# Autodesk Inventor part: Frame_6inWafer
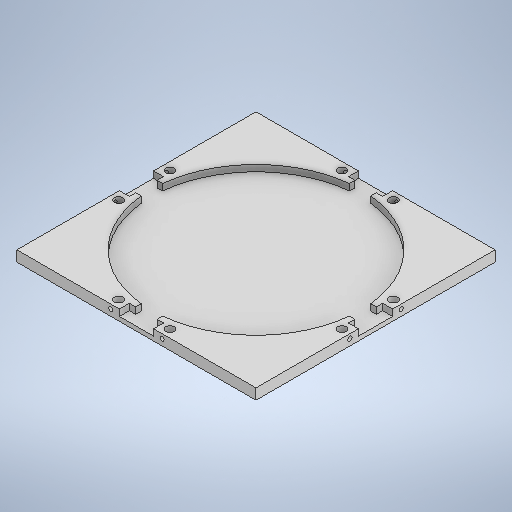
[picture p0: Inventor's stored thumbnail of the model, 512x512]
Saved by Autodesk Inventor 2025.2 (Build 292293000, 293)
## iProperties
Created: 2025-09
Part Number: Frame_6inWafer
Material: Generic
Document SubType Name: Modeling
Designer: tyler
Density: 1 g/cm^3
Appearance: Default
Author: tyler
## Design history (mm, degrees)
sketch "Sketch1"
  geometry: L1 (88.9, 88.9)-(88.9, -88.9); L2 (88.9, -88.9)-(-88.9, -88.9); L3 (-88.9, -88.9)-(-88.9, 88.9); L4 (-88.9, 88.9)-(88.9, -88.9); L5 (88.9, 88.9)-(-88.9, -88.9); L6 (0, 88.9)-(12.7, 88.9); L7 (12.7, 88.9)-(12.7, 76.744); L8 (0, 88.9)-(-12.7, 88.9); L9 (-12.7, 88.9)-(-12.7, 76.744); L10 (12.7, 81.506)-(7.938, 81.506); L11 (7.938, 81.506)-(7.938, 77.381); L12 (12.7, 76.744)-(12.7, 81.506); L13 (-12.7, 76.744)-(-12.7, 81.506); L14 (-12.7, 81.506)-(-7.938, 81.506); L15 (-7.938, 81.506)-(-7.938, 77.381); L16 (-88.9, 12.7)-(-76.744, 12.7); L17 (-81.506, 12.7)-(-81.506, 7.938); L18 (-81.506, 7.938)-(-77.381, 7.938); L19 (-88.9, 0)-(-88.9, 12.7); L20 (-88.9, 0)-(-88.9, -12.7); L21 (-88.9, -12.7)-(-76.744, -12.7); L22 (-81.506, -12.7)-(-81.506, -7.937); L23 (-81.506, -7.937)-(-77.381, -7.937); L24 (-12.7, -88.9)-(-12.7, -76.744); L25 (-12.7, -81.506)-(-7.938, -81.506); L26 (-7.938, -81.506)-(-7.938, -77.381); L27 (0, -88.9)-(-12.7, -88.9); L28 (0, -88.9)-(12.7, -88.9); L29 (12.7, -88.9)-(12.7, -76.744); L30 (12.7, -81.506)-(7.937, -81.506); L31 (7.937, -81.506)-(7.937, -77.381); L32 (88.9, -12.7)-(76.744, -12.7); L33 (81.506, -12.7)-(81.506, -7.938); L34 (81.506, -7.938)-(77.381, -7.938); L35 (88.9, 0)-(88.9, -12.7); L36 (88.9, 0)-(88.9, 12.7); L37 (88.9, 12.7)-(76.744, 12.7); L38 (81.506, 12.7)-(81.506, 7.937); L39 (81.506, 7.937)-(77.381, 7.937); L40 (88.9, 88.9)-(-88.9, 88.9); C1 r 76.2 at (0, 0); A1 r 77.788 centre (0, 0) between (12.7, 76.744) and (-12.7, 76.744); 15 further points
  constraints: 80 end point, 8 point on line, 5 perpendicular, 5 point on circle, 2 centre point, 2 coincident, 2 horizontal, 2 midpoint, 1 parallel, 1 vertical, 77 other
  dimensions: "d0" = 177.8 distance of L1.end L2.end; "d1" = 177.8 distance of L1.start L1.end; "d2" = 152.4 diameter of C1; "d3" = 155.575 diameter of A1; "d4" = 12.7 distance of L6.start L6.end; "d7" = 4.7625 distance of L10.start L10.end; "d8" = 4.7625 distance of L7.end L10.start; "d9" = 4.7625 distance of L13.end L14.end; "d12" = 360 deg dimension on point (0, 0) L6.end (derived)
  node "Sketch Circular Pattern1" dims "d12" = 360 deg (derived)
sketch "Sketch2"
  geometry: L1 (-88.9, -88.9)-(88.9, -88.9); L2 (88.9, -88.9)-(88.9, 88.9); L3 (88.9, 88.9)-(-88.9, 88.9); L4 (-88.9, 88.9)-(-88.9, -88.9); L5 (-88.9, -88.9)-(88.9, 88.9); L6 (88.9, -88.9)-(-88.9, 88.9); 1 further point
  constraints: 12 end point, 2 midpoint, 2 parallel, 1 horizontal, 1 perpendicular
  dimensions: "d14" = 177.8 distance of L3.end L2.end; "d15" = 177.8 distance of L2.end L1.end
extrude "Extrusion1" new body sketch "Sketch2" distance "d16" = 3.175; taper "d17" = 0 deg
extrude "Extrusion2" join sketch "Sketch1" distance "d18" = 4.7625; taper "d19" = 0 deg
sketch "Sketch3"
  geometry: L1 (0, -83.058)-(19.05, -83.058); L2 (0, -83.058)-(-19.05, -83.058); L3 (-12.7, -88.9)-(12.7, -88.9) reference; L4 (0, -88.9)-(0, -83.058); C1 r 3.175 at (-19.05, -83.058); C2 r 3.175 at (19.05, -83.058); C3 r 3.175 at (83.058, -19.05); C4 r 3.175 at (83.058, 19.05); C5 r 3.175 at (19.05, 83.058); C6 r 3.175 at (-19.05, 83.058); C7 r 3.175 at (-83.058, 19.05); C8 r 3.175 at (-83.058, -19.05); 1 further point
  constraints: 8 centre point, 6 end point, 2 coincident, 2 horizontal, 1 midpoint, 1 perpendicular, 17 other
  dimensions: "d29" = 19.05 distance of L1.start L1.end; "d30" = 19.05 distance of L1.start L2.end; "d31" = 6.35 diameter of C1; "d32" = 6.35 diameter of C2; "d33" = 5.842 distance of L4.start L1.start; "d36" = 360 deg dimension on point (0, 0) C1.centre (derived)
extrude "Extrusion3" cut sketch "Sketch3" distance "d38" = 6.35; taper "d39" = 0 deg
sketch "Sketch4"
  geometry: L1 (177.8, 0)-(0, 0) reference; L2 (88.9, 0)-(63.5, 0); L3 (88.9, 0)-(114.3, 0); L4 (63.5, 0)-(69.85, 0); L5 (114.3, 0)-(107.95, 0); L6 (0, 7.938)-(76.2, 7.938) reference; L7 (101.6, 7.938)-(177.8, 7.938) reference; C1 r 1.587 at (69.85, 4.762); C2 r 1.587 at (107.95, 4.762); 1 further point
  constraints: 8 end point, 4 point on line, 2 centre point, 1 midpoint
  dimensions: "d40" = 25.4 distance of L2.start L2.end; "d41" = 25.4 distance of L2.start L3.end; "d44" = 6.35 distance of L4.end L2.end; "d45" = 6.35 distance of L5.end L3.end; "d46" = 3.175 diameter of C1; "d47" = 3.175 diameter of C2; "d76" = 3.175 distance from line of C1.centre L6; "d77" = 3.175 distance from line of L7 C2.centre
extrude "Extrusion4" cut sketch "Sketch4" distance "d48" = 6.35; taper "d49" = 0 deg
sketch "Sketch5"
  geometry: L1 (177.8, 0)-(0, 0) reference; L2 (88.9, 0)-(63.5, 0); L3 (63.5, 0)-(63.5, 4.762); L4 (63.5, 4.762)-(69.85, 4.763); L5 (88.9, 0)-(114.3, 0); L6 (114.3, 3.175)-(107.95, 3.175); L7 (166.281, 3.175)-(96.838, 3.175) reference; L8 (0, 7.938)-(76.2, 7.938) reference; L9 (107.95, 7.938)-(107.95, 4.763); C1 r 1.588 at (69.85, 4.763); 2 further points
  constraints: 12 end point, 3 point on line, 2 coincident, 2 perpendicular, 1 centre point, 1 midpoint, 1 vertical, 1 vertical alignment, 2 other
  dimensions: "d50" = 25.4 distance of L2.start L2.end; "d52" = 6.35 distance of L3.end L4.end; "d56" = 3.175 diameter of C1; "d78" = 3.175 distance from line of L8 L4.end
extrude "Extrusion5" cut sketch "Sketch5" distance "d58" = 6.35; taper "d59" = 0 deg
sketch "Sketch6"
  geometry: L1 (0, 0)-(177.8, 0) reference; L2 (88.9, 0)-(63.5, 0); L3 (80.963, 3.175)-(11.519, 3.175) reference; L4 (69.85, 3.175)-(107.95, 3.175); L5 (166.281, 3.175)-(96.838, 3.175) reference; L6 (76.2, 7.938)-(0, 7.938) reference; L7 (69.85, 7.938)-(69.85, 4.763); L8 (104.775, 7.938)-(111.125, 7.938) reference; L9 (107.95, 7.938)-(107.95, 4.763); C1 r 1.587 at (69.85, 4.763); C2 r 1.588 at (107.95, 4.763); 1 further point
  constraints: 8 end point, 4 point on line, 2 centre point, 2 coincident, 2 midpoint, 1 vertical, 1 vertical alignment, 1 other
  dimensions: "d79" = 3.175 distance of L7.start L7.end; "d80" = 3.175 distance of L9.start L9.end (derived); "d81" = 3.175 diameter of C1
extrude "Extrusion6" cut sketch "Sketch6" distance "d66" = 6.35; taper "d67" = 0 deg
sketch "Sketch7"
  geometry: L1 (0, 0)-(177.8, 0) reference; L2 (88.9, 0)-(63.5, 0); L3 (63.5, 4.762)-(69.85, 4.762); L4 (69.85, 4.762)-(107.95, 4.762); L5 (69.85, 4.762)-(69.85, 7.938); L6 (66.675, 7.938)-(73.025, 7.938) reference; C1 r 1.587 at (69.85, 4.762); C2 r 1.587 at (107.95, 4.762); 1 further point
  constraints: 8 end point, 2 centre point, 2 coincident, 2 midpoint, 2 point on line
  dimensions: "d68" = 25.4 distance of L2.start L2.end; "d69" = 6.35 distance of L3.start L3.end; "d70" = 38.1 distance of L3.end L4.end; "d71" = 3.175 diameter of C1; "d72" = 3.175 diameter of C2; "d75" = 3.175 distance of L5.start L5.end
extrude "Extrusion7" cut sketch "Sketch7" distance "d73" = 6.35; taper "d74" = 0 deg
body "Solid1"
node "Sketch Circular Pattern2" dims "d36" = 360 deg (derived)
